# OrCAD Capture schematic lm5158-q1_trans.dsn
size Custom; title: LM5158x 2.2-MHz Wide VIN Boost/Sepic/Flyback Converter with; rev: 1.0; note: Datasheet: SNVSB88     EVM: NA; note: Synchronous Step Down Converter
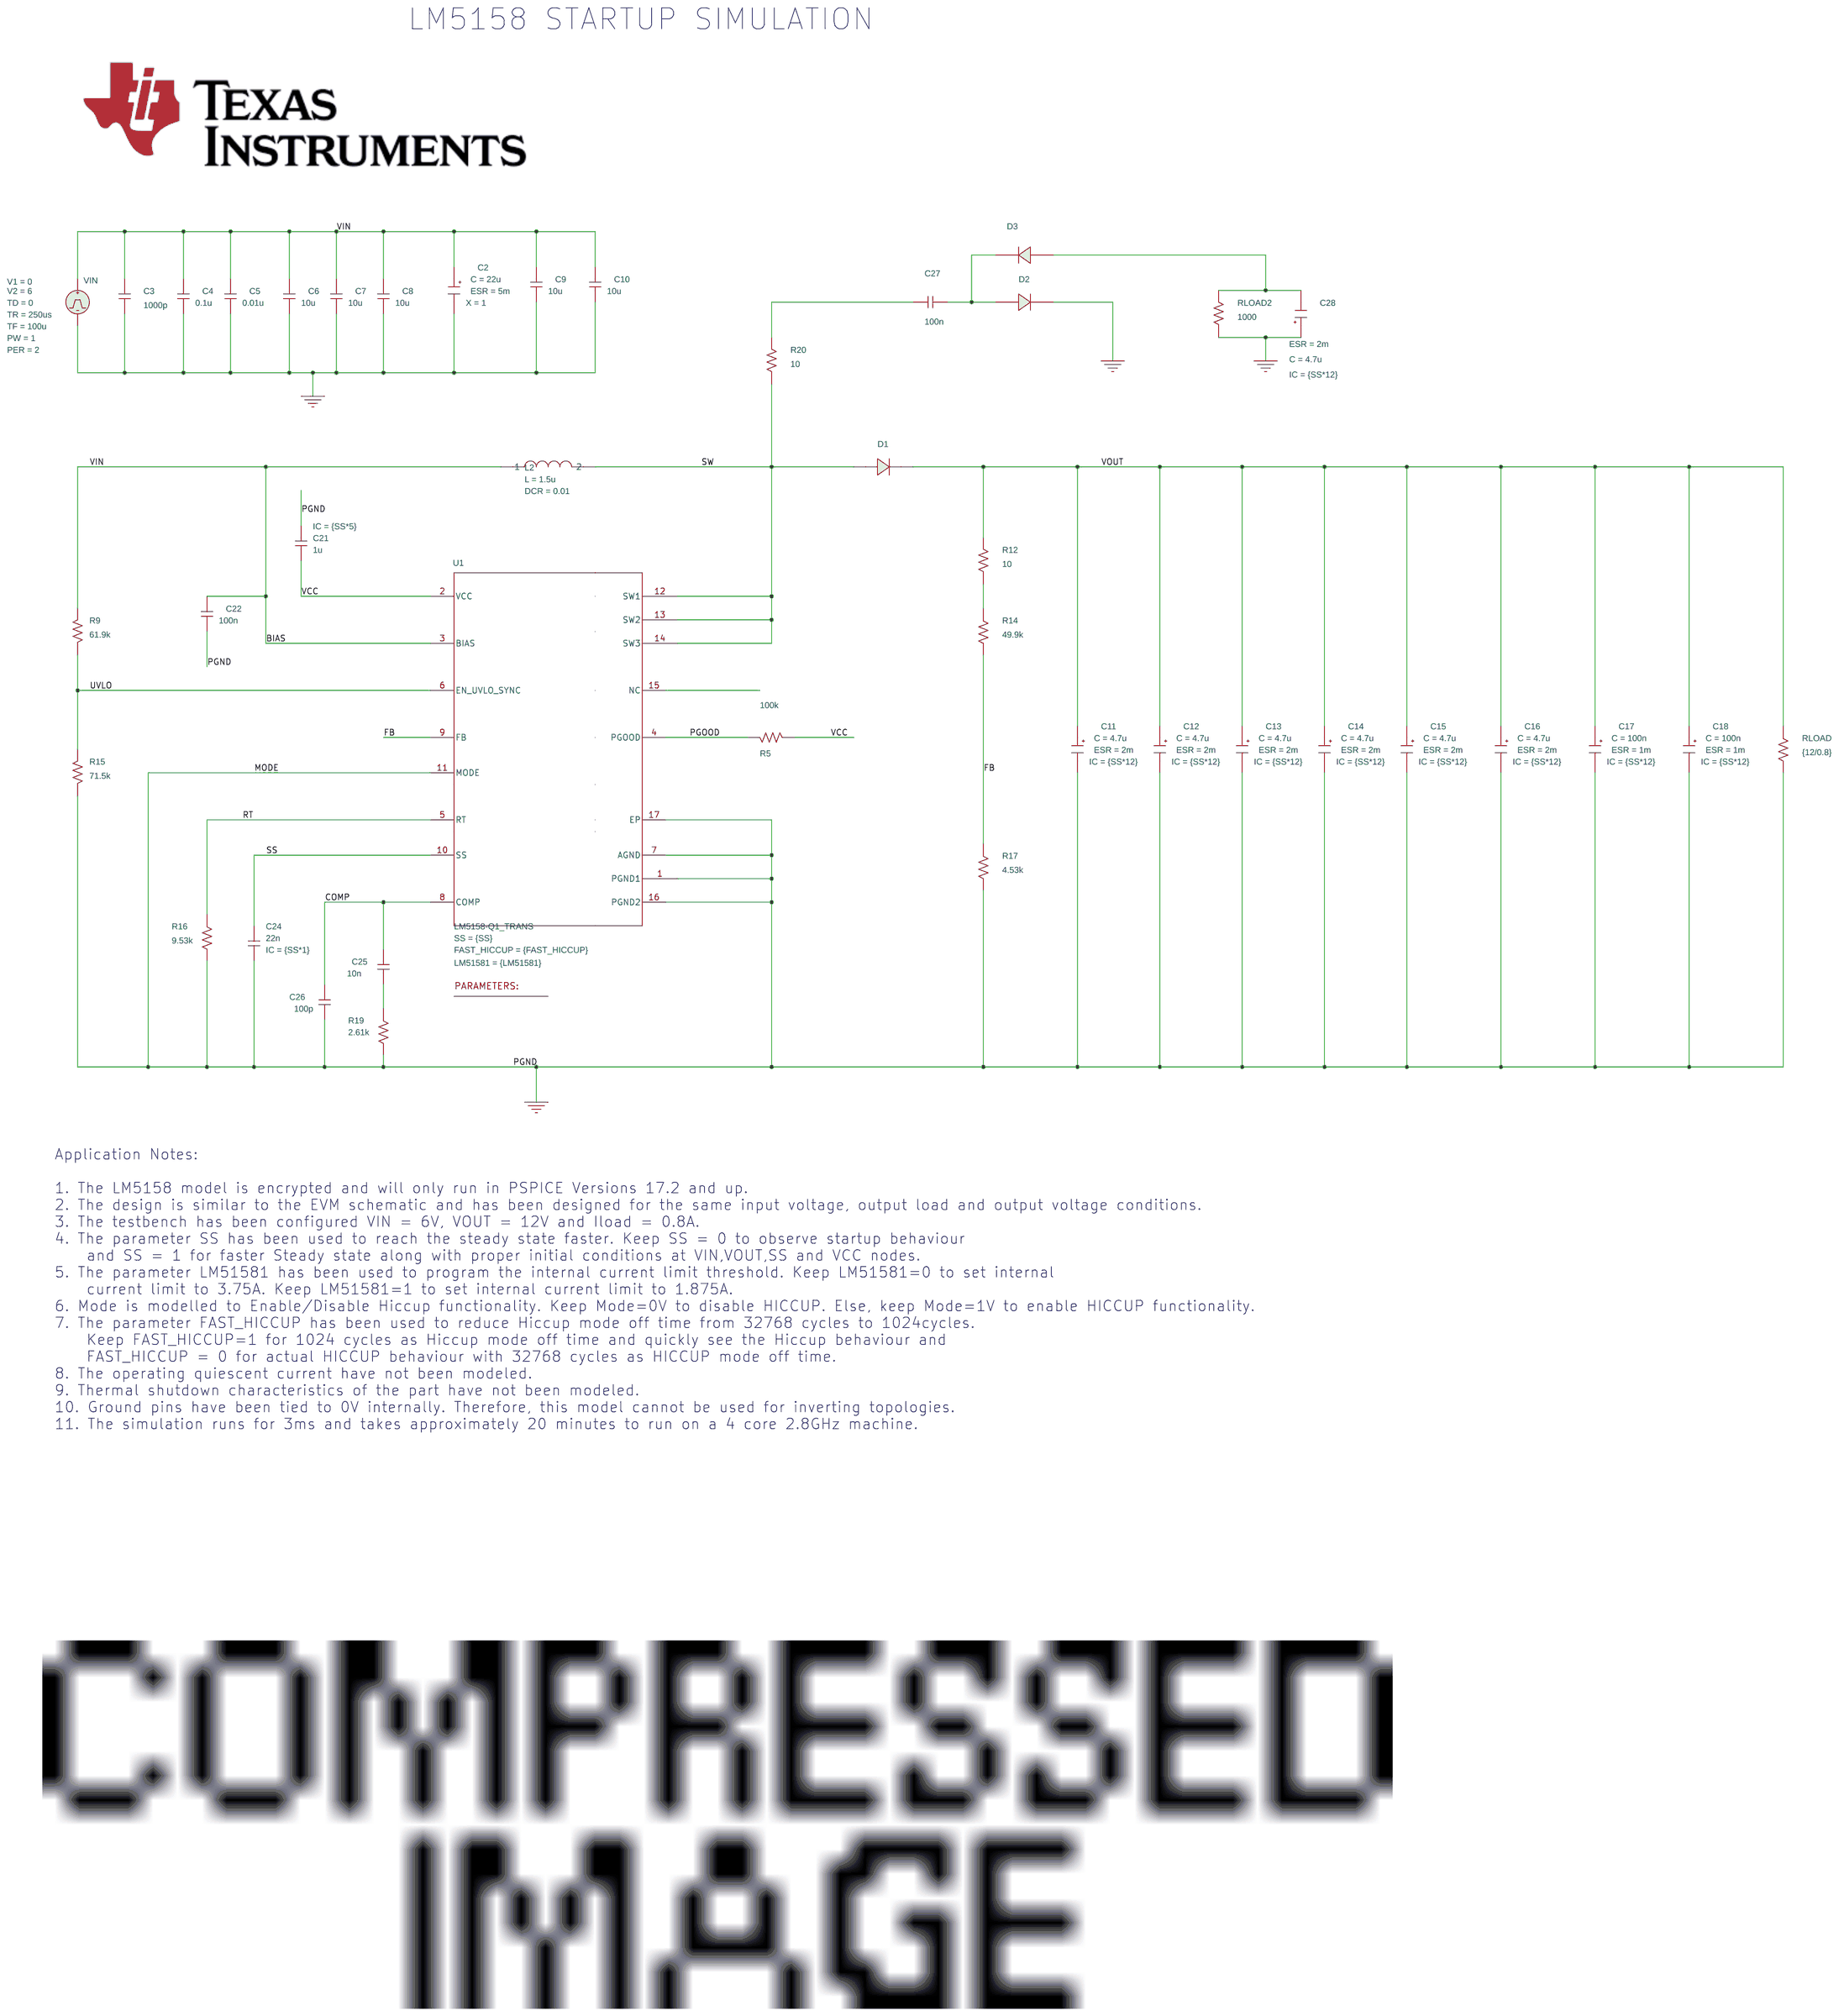
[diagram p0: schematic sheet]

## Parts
1  PARAM
C2  CESR
C3  1000p  [RAD/CK05]
C4  0.1u  [RAD/CK05]
C5  0.01u  [RAD/CK05]
C6  10u  [RAD/CK05]
C7  10u  [RAD/CK05]
C8  10u  [RAD/CK05]
C9  10u  [RAD/CK05]
C10  10u  [RAD/CK05]
C11  CESR
C12  CESR
C13  CESR
C14  CESR
C15  CESR
C16  CESR
C17  CESR
C18  CESR
C21  1u  [RAD/CK05]
C22  100n  [RAD/CK05]
C24  22n  [RAD/CK05]
C25  10n  [RAD/CK05]
C26  100p  [RAD/CK05]
C27  100n  [RAD/CK05]
C28  CESR
D1  PMEG060V100EPD
D2  PMEG060V100EPD
D3  PMEG060V100EPD
L2  LDCR
R5  100k  [AX/RC05]
R9  61.9k  [AX/RC05]
R12  10  [AX/RC05]
R14  49.9k  [AX/RC05]
R15  71.5k  [AX/RC05]
R16  9.53k  [AX/RC05]
R17  4.53k  [AX/RC05]
R19  2.61k  [AX/RC05]
R20  10  [AX/RC05]
RLOAD  {12/0.8}  [AX/RC05]
RLOAD2  1000  [AX/RC05]
U1  LM5158-Q1_TRANS  [DSS0012C]
VIN  VPULSE

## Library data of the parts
1 = PARAM: LM51581: 0; SS: 0
C2 = CESR_0: C: 22u; ESR: 5m; IC: {SS*10}; PSpiceTemplate: X^@REFDES %IN %OUT @MODEL PARAMS:  ?C|C=@C||C=100u|  ?ESR|ESR=@ESR||ESR=0.01| ?X|X=@X||X=2|  ?IC|IC=@IC||IC=2|; X: 1
C3-C10 C22 C25-C27 = C
C11-C16 C28 = CESR_0: C: 4.7u; ESR: 2m; IC: {SS*12}; PSpiceTemplate: X^@REFDES %IN %OUT @MODEL PARAMS:  ?C|C=@C||C=100u|  ?ESR|ESR=@ESR||ESR=0.01| ?X|X=@X||X=2|  ?IC|IC=@IC||IC=2|; X: 1
C17 C18 = CESR_0: C: 100n; ESR: 1m; IC: {SS*12}; PSpiceTemplate: X^@REFDES %IN %OUT @MODEL PARAMS:  ?C|C=@C||C=100u|  ?ESR|ESR=@ESR||ESR=0.01| ?X|X=@X||X=2|  ?IC|IC=@IC||IC=2|; X: 1
C21 = C: IC: {SS*5}
C24 = C: IC: {SS*1}
D1-D3 = D_D1
L2 = LDCR: DCR: 0.01; L: 1.5u
R5 R9 R12 R14-R17 R19 R20 RLOAD RLOAD2 = R
U1 = LM5158-Q1_TRANS: FAST_HICCUP: {FAST_HICCUP}; LM51581: {LM51581}; SS: {SS}
VIN = VPULSE: PER: 2; PW: 1; TD: 0; TF: 100u; TR: 250us; V1: 0; V2: 6

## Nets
VCC: C21.1 R5.1 U1.2(VCC)
0: C2.2(OUT) C3.2 C4.2 C5.2 C6.2 C7.2 C8.2 C9.2 C10.2 C11.2(OUT) C12.2(OUT) C13.2(OUT) C14.2(OUT) C15.2(OUT) C16.2(OUT) C17.2(OUT) C18.2(OUT) C21.2 C22.2 C24.2 C26.2 C28.1(IN) D2.1(C) R15.1 R16.2 R17.2 R19.2 RLOAD.2 RLOAD2.1 U1.1(PGND1) U1.7(AGND) U1.11(MODE) U1.16(PGND2) U1.17(EP) VIN.2(-)
BIAS: C2.1(IN) C3.1 C4.1 C5.1 C6.1 C7.1 C8.1 C9.1 C10.1 C22.1 L2.1 R9.2 U1.3(BIAS) VIN.1(+)
COMP: C25.1 C26.1 U1.8(COMP)
FB: R14.2 R17.1 U1.9(FB)
PGOOD: R5.2 U1.4(PGOOD)
RT: R16.1 U1.5(RT)
SS: C24.1 U1.10(SS)
SW: D1.2(A) L2.2 R20.1 U1.12(SW1) U1.13(SW2) U1.14(SW3)
UVLO: R9.1 R15.2 U1.6(EN_UVLO_SYNC)
VOUT: C11.1(IN) C12.1(IN) C13.1(IN) C14.1(IN) C15.1(IN) C16.1(IN) C17.1(IN) C18.1(IN) D1.1(C) R12.2 RLOAD.1
N16794806: R12.1 R14.1
N16795152: C25.2 R19.1
N16798997: C27.1 R20.2
N16799252: C27.2 D2.2(A) D3.1(C)
N16799264: C28.2(OUT) D3.2(A) RLOAD2.2

Not connected (* = marked no-connect by the designer): U1 15(NC)

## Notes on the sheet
- LM5158 STARTUP SIMULATION
- Application Notes:
  1. The LM5158 model is encrypted and will only run in PSPICE Versions 17.2 and up.
  2. The design is similar to the EVM schematic and has been designed for the same input voltage, output load and output voltage conditions.
  3. The testbench has been configured VIN = 6V, VOUT = 12V and Iload = 0.8A.
  4. The parameter SS has been used to reach the steady state faster. Keep SS = 0 to observe startup behaviour
      and SS = 1 for faster Steady state along with proper initial conditions at VIN,VOUT,SS and VCC nodes.
  5. The parameter LM51581 has been used to program the internal current limit threshold. Keep LM51581=0 to set internal
      current limit to 3.75A. Keep LM51581=1 to set internal current limit to 1.875A.
  6. Mode is modelled to Enable/Disable Hiccup functionality. Keep Mode=0V to disable HICCUP. Else, keep Mode=1V to enable HICCUP functionality.
  7. The parameter FAST_HICCUP has been used to reduce Hiccup mode off time from 32768 cycles to 1024cycles.
      Keep FAST_HICCUP=1 for 1024 cycles as Hiccup mode off time and quickly see the Hiccup behaviour and
      FAST_HICCUP = 0 for actual HICCUP behaviour with 32768 cycles as HICCUP mode off time.
  8. The operating quiescent current have not been modeled.
  9. Thermal shutdown characteristics of the part have not been modeled.
  10. Ground pins have been tied to 0V internally. Therefore, this model cannot be used for inverting topologies.
  11. The simulation runs for 3ms and takes approximately 20 minutes to run on a 4 core 2.8GHz machine.
